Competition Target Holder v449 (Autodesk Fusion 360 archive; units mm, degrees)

design "Rifle Target Holder"
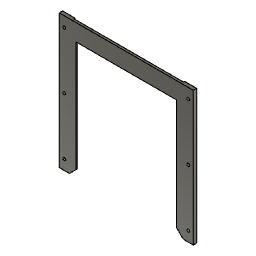
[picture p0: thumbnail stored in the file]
sketch "Sketch1" plane through (0, 0, 0) normal (0, 1, 0) x axis (1, 0, 0)
  line L1 (-174.5899, -63.5422) -> (-54.5899, -63.5422)
  line L2 (-174.5899, -183.5422) -> (-174.5899, -63.5422)
  line L3 (-54.5899, -183.5422) -> (-174.5899, -183.5422)
  line L4 (-54.5899, -63.5422) -> (-54.5899, -183.5422)
  line L5 (-69.5899, -168.5422) -> (-159.5899, -168.5422)
  line L6 (-69.5899, -78.5422) -> (-69.5899, -168.5422)
  line L7 (-159.5899, -78.5422) -> (-69.5899, -78.5422)
  line L8 (-159.5899, -168.5422) -> (-159.5899, -78.5422)
  line L9 (-159.5899, -183.5422) -> (-174.5899, -183.5422)
  line L10 (-174.5899, -183.5422) -> (-174.5899, -168.5422)
  point P2 (-54.5899, -63.5422)
  point P3 (-174.5899, -63.5422)
  point P5 (-54.5899, -183.5422)
  point P6 (-159.5899, -168.5422)
  point P7 (-69.5899, -168.5422)
  point P9 (-159.5899, -78.5422)
  point P4 (-174.5899, -183.5422)
  point P10 (-159.5899, -183.5422)
  point P11 (-174.5899, -168.5422)
  horizontal L1
  vertical L2
  horizontal L3
  vertical L4
  horizontal L5
  vertical L6
  horizontal L7
  vertical L8
  horizontal L9
  vertical L10
  dimension "d1" distance P2 P3 = 120
  dimension "d2" distance P2 P5 = 120
  dimension "d3" distance P6 P7 = 90
  dimension "d4" distance P6 P9 = 90
  dimension "d5" distance P4 P10 = 15
  dimension "d6" distance P4 P11 = 15
extrude "Extrude1" new body sketch "Sketch1" along normal blind 5
sketch "Sketch2" plane through (0, 0, 183.5422) normal (0, 0, 1) x axis (-1, 0, 0)
sketch "Sketch3" plane through (0, 0, 183.5422) normal (0, 0, 1) x axis (-1, 0, 0)
sketch "Sketch4" plane through (0, 0, 0) normal (0, 0, 1) x axis (1, 0, 0)
sketch "Sketch5" plane through (0, 0, 0) normal (0, 0, 1) x axis (1, 0, 0)
  line L1 (-63.5899, 5) -> (-165.5899, 5)
  line L2 (-63.5899, 3) -> (-63.5899, 5)
  line L3 (-165.5899, 3) -> (-63.5899, 3)
  line L4 (-165.5899, 5) -> (-165.5899, 3)
  line L5 (-174.5899, 5) -> (-54.5899, 5)
  point P2 (-165.5899, 5)
  point P3 (-63.5899, 5)
  point P5 (-165.5899, 3)
  horizontal L1
  vertical L2
  horizontal L3
  vertical L4
  midpoint L1 L5
  dimension "d14" distance P2 P3 = 102
  dimension "d15" distance P2 P5 = 2
extrude "Extrude2" cut sketch "Sketch5" to an object
sketch "Sketch6" plane through (0, 0, 183.5422) normal (0, 0, 1) x axis (-1, 0, 0)
  line L1 (63.5899, -3) -> (165.5899, -3)
  line L2 (63.5899, -4) -> (63.5899, -3)
  line L3 (165.5899, -4) -> (63.5899, -4)
  line L4 (165.5899, -3) -> (165.5899, -4)
  line L5 (63.5899, -3) -> (165.5899, -3)
  point P2 (165.5899, -3)
  point P3 (63.5899, -3)
  point P5 (165.5899, -4)
  horizontal L1
  vertical L2
  horizontal L3
  vertical L4
  midpoint L1 L5
  dimension "d18" distance P2 P3 = 102
  dimension "d19" distance P2 P5 = 1
extrude "Extrude3" add sketch "Sketch6" against normal blind 9
sketch "Sketch7" plane through (0, 5, 0) normal (0, 1, 0) x axis (-1, 0, 0)
  line L1 (63.5899, 183.5422) -> (63.5899, 63.5422)
  line L2 (54.5899, 183.5422) -> (63.5899, 183.5422)
  line L3 (54.5899, 63.5422) -> (54.5899, 183.5422)
  line L4 (63.5899, 63.5422) -> (54.5899, 63.5422)
  line L5 (69.5899, 168.5422) -> (159.5899, 168.5422)
  line L6 (159.5899, 78.5422) -> (69.5899, 78.5422)
  circle C1 centre (170.0899, 123.4348) radius 1.5
  circle C2 centre (170.0899, 174.4348) radius 1.5
  circle C3 centre (59.0899, 174.4348) radius 1.5
  circle C4 centre (170.0899, 72.4348) radius 1.5
  circle C5 centre (59.0899, 72.4348) radius 1.5
  circle C6 centre (59.0899, 123.4348) radius 1.5
  dimension "d34" diameter C1 = 3
  dimension "d35" diameter C2 = 3
  dimension "d36" diameter C3 = 3
  dimension "d37" diameter C4 = 3
  dimension "d38" diameter C5 = 3
  dimension "d39" diameter C6 = 3
extrude "Extrude4" cut sketch "Sketch7" profile of C1 C2 C3 C4 C5 C6 against normal blind 5
sketch "Sketch8" plane through (0, 0, 0) normal (0, 1, 0) x axis (1, 0, 0)
sketch "Sketch9" plane through (0, 4, 0) normal (0, 1, 0) x axis (-1, 0, 0)
sketch "Sketch10" plane through (0, 5, 0) normal (0, 1, 0) x axis (-1, 0, 0)
  line L1 (165.5899, 63.5422) -> (165.5899, 183.5422)
  line L2 (174.5899, 63.5422) -> (165.5899, 63.5422)
  line L3 (174.5899, 183.5422) -> (174.5899, 63.5422)
  line L4 (165.5899, 183.5422) -> (174.5899, 183.5422)
  line L5 (170.0899, 168.9348) -> (165.5899, 168.9348)
  line L6 (170.0899, 128.9348) -> (170.0899, 168.9348)
  line L7 (165.5899, 128.9348) -> (170.0899, 128.9348)
  line L8 (165.5899, 168.9348) -> (165.5899, 128.9348)
  line L9 (165.5899, 117.9348) -> (170.0899, 117.9348)
  line L10 (165.5899, 77.9348) -> (165.5899, 117.9348)
  line L11 (170.0899, 77.9348) -> (165.5899, 77.9348)
  line L12 (170.0899, 117.9348) -> (170.0899, 77.9348)
  circle C1 centre (170.0899, 72.4348) radius 1.5
  circle C2 centre (170.0899, 123.4348) radius 1.5
  circle C3 centre (170.0899, 174.4348) radius 1.5
  point P9 (165.5899, 168.9348)
  point P10 (170.0899, 168.9348)
  point P12 (165.5899, 128.9348)
  point P13 (170.0899, 117.9348)
  point P14 (165.5899, 117.9348)
  point P16 (170.0899, 77.9348)
  horizontal L5
  vertical L6
  horizontal L7
  vertical L8
  coincident L1 P9
  horizontal L9
  vertical L10
  horizontal L11
  vertical L12
  dimension "d44" distance P9 P10 = 4.5
  dimension "d45" distance P9 P12 = 40
  dimension "d46" distance P13 P14 = 4.5
  dimension "d47" distance P13 P16 = 40
extrude "Extrude5" cut sketch "Sketch10" profile of L1 L5 L6 L7 L8 L9 L10 L11 L12 against normal blind 2
sketch "Sketch11" plane through (0, 5, 0) normal (0, 1, 0) x axis (-1, 0, 0)
  line L1 (165.5899, 128.9348) -> (170.0899, 128.9348)
  line L2 (165.5899, 117.9348) -> (165.5899, 128.9348)
  line L3 (170.0899, 117.9348) -> (165.5899, 117.9348)
  line L4 (170.0899, 77.9348) -> (170.0899, 117.9348)
  line L5 (165.5899, 77.9348) -> (170.0899, 77.9348)
  line L6 (165.5899, 63.5422) -> (165.5899, 77.9348)
  line L7 (174.5899, 63.5422) -> (165.5899, 63.5422)
  line L8 (174.5899, 183.5422) -> (174.5899, 63.5422)
  line L9 (165.5899, 183.5422) -> (174.5899, 183.5422)
  line L10 (165.5899, 168.9348) -> (165.5899, 183.5422)
  line L11 (170.0899, 168.9348) -> (165.5899, 168.9348)
  line L12 (170.0899, 128.9348) -> (170.0899, 168.9348)
  line L13 (164.0899, 168.9348) -> (170.0899, 168.9348)
  line L14 (164.0899, 128.9348) -> (164.0899, 168.9348)
  line L15 (170.0899, 128.9348) -> (164.0899, 128.9348)
  line L16 (170.0899, 168.9348) -> (170.0899, 128.9348)
  line L17 (164.0899, 117.9348) -> (170.0899, 117.9348)
  line L18 (164.0899, 77.9348) -> (164.0899, 117.9348)
  line L19 (170.0899, 77.9348) -> (164.0899, 77.9348)
  line L20 (170.0899, 117.9348) -> (170.0899, 77.9348)
  circle C1 centre (170.0899, 72.4348) radius 1.5
  circle C2 centre (170.0899, 123.4348) radius 1.5
  circle C3 centre (170.0899, 174.4348) radius 1.5
  point P13 (170.0899, 168.9348)
  point P17 (170.0899, 168.9348)
  point P5 (170.0899, 117.9348)
  point P21 (170.0899, 117.9348)
  point P18 (164.0899, 168.9348)
  point P20 (170.0899, 128.9348)
  point P22 (164.0899, 117.9348)
  point P24 (170.0899, 77.9348)
  horizontal L13
  vertical L14
  horizontal L15
  vertical L16
  coincident P13 P17
  horizontal L17
  vertical L18
  horizontal L19
  vertical L20
  coincident P5 P21
  dimension "d50" distance P17 P18 = 6
  dimension "d51" distance P17 P20 = 40
  dimension "d52" distance P21 P22 = 6
  dimension "d53" distance P21 P24 = 40
extrude "Extrude6" cut sketch "Sketch11" profile of L1 L3 L4 L5 L11 L12 L13 L14 L15 L16 L17 L18 L19 L20 against normal blind 3
sketch "Sketch27" plane through (0, 0, 183.5422) normal (0, 0, 1) x axis (-1, 0, 0)
  line L1 (51.2268, 0) -> (175, 0)
  line L2 (51.2268, -2) -> (51.2268, 0)
  line L3 (175, -2) -> (51.2268, -2)
  line L4 (175, 0) -> (175, -2)
  point P2 (175, 0)
  point P5 (175, -2)
  horizontal L1
  vertical L2
  horizontal L3
  vertical L4
  dimension "d99" distance P2 P5 = 2
extrude "Extrude11" cut sketch "Sketch27" against normal blind 200
sketch "Sketch28" plane through (0, 2, 0) normal (0, -1, 0) x axis (1, 0, 0)
  line L1 (-174.5899, 63.5422) -> (-174.5899, 183.5422)
  line L2 (-54.5899, 63.5422) -> (-174.5899, 63.5422)
  line L3 (-54.5899, 183.5422) -> (-54.5899, 63.5422)
  line L4 (-174.5899, 183.5422) -> (-54.5899, 183.5422)
  line L5 (-164.0899, 77.9348) -> (-164.0899, 117.9348)
  line L6 (-170.0899, 77.9348) -> (-164.0899, 77.9348)
  line L7 (-170.0899, 117.9348) -> (-170.0899, 77.9348)
  line L8 (-164.0899, 117.9348) -> (-170.0899, 117.9348)
  line L9 (-170.0899, 168.9348) -> (-170.0899, 128.9348)
  line L10 (-164.0899, 168.9348) -> (-170.0899, 168.9348)
  line L11 (-164.0899, 128.9348) -> (-164.0899, 168.9348)
  line L12 (-170.0899, 128.9348) -> (-164.0899, 128.9348)
  line L13 (-159.5899, 78.5422) -> (-69.5899, 78.5422)
  line L14 (-159.5899, 168.5422) -> (-159.5899, 78.5422)
  line L15 (-69.5899, 168.5422) -> (-159.5899, 168.5422)
  line L16 (-69.5899, 78.5422) -> (-69.5899, 168.5422)
  line L17 (-164.0899, 168.9348) -> (-170.0899, 168.9348)
  line L18 (-164.0899, 128.9348) -> (-164.0899, 168.9348)
  line L19 (-170.0899, 128.9348) -> (-164.0899, 128.9348)
  line L20 (-170.0899, 168.9348) -> (-170.0899, 128.9348)
  line L21 (-164.0899, 117.9348) -> (-170.0899, 117.9348)
  line L22 (-164.0899, 77.9348) -> (-164.0899, 117.9348)
  line L23 (-170.0899, 77.9348) -> (-164.0899, 77.9348)
  line L24 (-170.0899, 117.9348) -> (-170.0899, 77.9348)
  circle C1 centre (-170.0899, 72.4348) radius 1.5
  circle C2 centre (-59.0899, 174.4348) radius 1.5
  circle C3 centre (-170.0899, 123.4348) radius 1.5
  circle C4 centre (-59.0899, 72.4348) radius 1.5
  circle C5 centre (-59.0899, 123.4348) radius 1.5
  circle C6 centre (-170.0899, 174.4348) radius 1.5
  point P13 (-164.0899, 128.9348)
  point P26 (-164.0899, 128.9348)
  point P11 (-170.0899, 168.9348)
  point P24 (-170.0899, 168.9348)
  point P7 (-164.0899, 77.9348)
  point P30 (-164.0899, 77.9348)
  point P9 (-170.0899, 117.9348)
  point P28 (-170.0899, 117.9348)
  horizontal L17
  vertical L18
  horizontal L19
  vertical L20
  coincident P13 P26
  coincident P11 P24
  horizontal L21
  vertical L22
  horizontal L23
  vertical L24
  coincident P7 P30
  coincident P9 P28
extrude "Extrude12" add sketch "Sketch28" profile of L5 L6 L7 L8 L9 L10 L11 L12 L17 L18 L19 L20 L21 L22 L23 L24 to an object
sketch "Sketch29" plane through (0, 5, 0) normal (0, 1, 0) x axis (-1, 0, 0)
sketch "Sketch30" plane through (0, 5, 0) normal (0, 1, 0) x axis (-1, 0, 0)
  line L1 (165.5899, 168.9348) -> (158.5899, 168.9348)
  line L2 (165.5899, 128.9348) -> (165.5899, 168.9348)
  line L3 (158.5899, 128.9348) -> (165.5899, 128.9348)
  line L4 (158.5899, 168.9348) -> (158.5899, 128.9348)
  line L5 (165.5899, 117.9348) -> (158.5899, 117.9348)
  line L6 (165.5899, 77.9348) -> (165.5899, 117.9348)
  line L7 (158.5899, 77.9348) -> (165.5899, 77.9348)
  line L8 (158.5899, 117.9348) -> (158.5899, 77.9348)
  point P3 (165.5899, 168.9348)
  point P6 (165.5899, 168.9348)
  point P8 (165.5899, 117.9348)
  point P11 (165.5899, 117.9348)
  point P2 (158.5899, 168.9348)
  point P5 (158.5899, 128.9348)
  point P7 (158.5899, 117.9348)
  point P10 (158.5899, 77.9348)
  horizontal L1
  vertical L2
  horizontal L3
  vertical L4
  coincident P3 P6
  horizontal L5
  vertical L6
  horizontal L7
  vertical L8
  coincident P8 P11
  dimension "d104" distance P2 P5 = 40
  dimension "d105" distance P7 P10 = 40
extrude "Extrude13" cut sketch "Sketch30" to an object
sketch "Sketch31" plane through (0, 3, 0) normal (0, 1, 0) x axis (-1, 0, 0)
  line L1 (159.5899, 78.5422) -> (159.5899, 168.5422)
  line L2 (69.5899, 78.5422) -> (159.5899, 78.5422)
  line L3 (69.5899, 168.5422) -> (69.5899, 78.5422)
  line L4 (159.5899, 168.5422) -> (69.5899, 168.5422)
  line L5 (165.5899, 174.5422) -> (165.5899, 63.5422)
  line L6 (63.5899, 174.5422) -> (165.5899, 174.5422)
  line L7 (63.5899, 63.5422) -> (63.5899, 174.5422)
  line L8 (165.5899, 63.5422) -> (63.5899, 63.5422)
  line L9 (159.5899, 78.5422) -> (69.5899, 78.5422)
  line L10 (159.5899, 55) -> (159.5899, 78.5422)
  line L11 (69.5899, 55) -> (159.5899, 55)
  line L12 (69.5899, 78.5422) -> (69.5899, 55)
  point P4 (69.5899, 78.5422)
  point P10 (69.5899, 78.5422)
  point P11 (159.5899, 78.5422)
  horizontal L9
  vertical L10
  horizontal L11
  vertical L12
  coincident P4 P10
  dimension "d108" distance P10 P11 = 90
extrude "Extrude14" cut sketch "Sketch31" profile of L2 L8 L9 L10 L12 to an object
sketch "Sketch32" plane through (0, 2, 0) normal (0, -1, 0) x axis (1, 0, 0)
  line L1 (-159.5899, 168.5422) -> (-159.5899, 63.5422)
  line L2 (-69.5899, 168.5422) -> (-159.5899, 168.5422)
  line L3 (-69.5899, 63.5422) -> (-69.5899, 168.5422)
  line L4 (-54.5899, 63.5422) -> (-69.5899, 63.5422)
  line L5 (-54.5899, 183.5422) -> (-54.5899, 63.5422)
  line L6 (-174.5899, 183.5422) -> (-54.5899, 183.5422)
  line L7 (-174.5899, 63.5422) -> (-174.5899, 183.5422)
  line L8 (-159.5899, 63.5422) -> (-174.5899, 63.5422)
  line L9 (-82.2581, 82.2104) -> (-63.5899, 63.5422)
  line L10 (-37.1892, 63.5422) -> (-63.5899, 63.5422)
  line L11 (-163.7719, 64.5857) -> (-163.7719, 63.5422)
  line L12 (-151.5827, 77.5225) -> (-165.563, 63.5422)
  line L13 (-185.334, 63.5422) -> (-165.563, 63.5422)
  line L14 (-151.5827, 77.5225) -> (-82.2581, 82.2104)
  line L15 (-165.563, 63.5422) -> (-63.5899, 63.5422)
  circle C1 centre (-170.0899, 174.4348) radius 1.5
  circle C2 centre (-59.0899, 123.4348) radius 1.5
  circle C3 centre (-59.0899, 72.4348) radius 1.5
  circle C4 centre (-170.0899, 123.4348) radius 1.5
  circle C5 centre (-59.0899, 174.4348) radius 1.5
  circle C6 centre (-170.0899, 72.4348) radius 1.5
  point P16 (-63.5899, 63.5422)
  point P19 (-63.5899, 63.5422)
  point P20 (-163.7719, 63.5422)
  point P22 (-165.563, 63.5422)
  horizontal L10
  coincident L4 P16
  coincident P16 P19
  coincident L8 P20
  perpendicular L8 L11
  horizontal L13
  coincident L8 P22
  dimension "d111" angle L9 L10 = 135
  dimension "d113" angle L12 L13 = 135
extrude "Extrude15" cut sketch "Sketch32" profile of L1 L3 L4 L8 L9 L12 L15 to an object
sketch "Sketch33" plane through (0, 4, 0) normal (0, 1, 0) x axis (-1, 0, 0)
  line L1 (63.5899, 183.5422) -> (165.5899, 183.5422)
  line L2 (63.5899, 174.5422) -> (63.5899, 183.5422)
  line L3 (165.5899, 174.5422) -> (63.5899, 174.5422)
  line L4 (165.5899, 183.5422) -> (165.5899, 174.5422)
  line L5 (160.5899, 183.5422) -> (68.5899, 183.5422)
  line L6 (160.5899, 168.5422) -> (160.5899, 183.5422)
  line L7 (68.5899, 168.5422) -> (160.5899, 168.5422)
  line L8 (68.5899, 183.5422) -> (68.5899, 168.5422)
  line L9 (68.5899, 183.5422) -> (63.5899, 183.5422)
  line L10 (68.5899, 174.5422) -> (68.5899, 183.5422)
  line L11 (63.5899, 174.5422) -> (68.5899, 174.5422)
  line L12 (63.5899, 183.5422) -> (63.5899, 174.5422)
  line L13 (160.5899, 183.5422) -> (165.5899, 183.5422)
  line L14 (160.5899, 174.5422) -> (160.5899, 183.5422)
  line L15 (165.5899, 174.5422) -> (160.5899, 174.5422)
  line L16 (165.5899, 183.5422) -> (165.5899, 174.5422)
  point P12 (68.5899, 174.5422)
  point P3 (63.5899, 183.5422)
  point P10 (63.5899, 183.5422)
  point P16 (160.5899, 174.5422)
  point P2 (165.5899, 183.5422)
  point P14 (165.5899, 183.5422)
  point P6 (68.5899, 183.5422)
  point P7 (160.5899, 183.5422)
  horizontal L5
  vertical L6
  horizontal L7
  vertical L8
  midpoint L1 L5
  horizontal L9
  vertical L10
  horizontal L11
  vertical L12
  coincident L3 P12
  coincident L8 P12
  coincident P3 P10
  horizontal L13
  vertical L14
  horizontal L15
  vertical L16
  coincident L3 P16
  coincident L6 P16
  coincident P2 P14
  dimension "d116" distance P6 P7 = 92
extrude "Extrude16" add sketch "Sketch33" profile of L1 L2 L3 L4 L6 L8 L9 L10 L11 L12 L13 L14 L15 L16 along normal blind 1
sketch "Sketch34" plane through (0, 4, 0) normal (0, 1, 0) x axis (-1, 0, 0)
  line L1 (160.5899, 183.5422) -> (160.5899, 174.5422)
  line L2 (68.5899, 183.5422) -> (160.5899, 183.5422)
  line L3 (68.5899, 174.5422) -> (68.5899, 183.5422)
  line L4 (160.5899, 174.5422) -> (68.5899, 174.5422)
  line L5 (163.5899, 168.5422) -> (65.5899, 168.5422)
  line L6 (163.5899, 183.5422) -> (163.5899, 168.5422)
  line L7 (65.5899, 183.5422) -> (163.5899, 183.5422)
  line L8 (65.5899, 168.5422) -> (65.5899, 183.5422)
  point P6 (65.5899, 168.5422)
  point P7 (163.5899, 168.5422)
  horizontal L5
  vertical L6
  horizontal L7
  vertical L8
  midpoint L2 L7
  dimension "d119" distance P6 P7 = 98
extrude "Extrude17" cut sketch "Sketch34" profile of L1 L3 L4 L5 L6 L7 L8 along normal blind 1
sketch "Sketch35" plane through (0, 5, 0) normal (0, 1, 0) x axis (-1, 0, 0)
  line L1 (163.5899, 174.5422) -> (163.5899, 183.5422)
  line L2 (165.5899, 174.5422) -> (163.5899, 174.5422)
  line L3 (165.5899, 63.5422) -> (165.5899, 174.5422)
  line L4 (174.5899, 63.5422) -> (165.5899, 63.5422)
  line L5 (174.5899, 183.5422) -> (174.5899, 63.5422)
  line L6 (163.5899, 183.5422) -> (174.5899, 183.5422)
  line L7 (170.0899, 123.4348) -> (170.0899, 174.4348)
  line L8 (170.0899, 72.4348) -> (170.0899, 123.4348)
  line L9 (144.5169, 151.2369) -> (170.0899, 151.2369)
  line L10 (144.5169, 97.9348) -> (170.0899, 97.9348)
  circle C1 centre (170.0899, 174.4348) radius 1.5
  circle C2 centre (170.0899, 123.4348) radius 1.5
  circle C3 centre (170.0899, 72.4348) radius 1.5
  circle C4 centre (165.5899, 151.2369) radius 1
  circle C5 centre (165.5899, 97.9348) radius 1
  point P2 (170.0899, 174.4348)
  point P11 (170.0899, 174.4348)
  point P3 (170.0899, 123.4348)
  point P12 (170.0899, 123.4348)
  point P4 (170.0899, 72.4348)
  point P13 (170.0899, 72.4348)
  point P14 (170.0899, 151.2369)
  point P16 (170.0899, 97.9348)
  point P18 (165.5899, 151.2369)
  point P19 (165.5899, 97.9348)
  coincident P2 P11
  coincident P3 P12
  coincident P4 P13
  coincident L7 P14
  perpendicular L7 L9
  midpoint L8 P16
  perpendicular L8 L10
  coincident L3 P18
  coincident L9 P18
  coincident L3 P19
  coincident L10 P19
  dimension "d122" diameter C4 = 2
  dimension "d123" diameter C5 = 2
sketch "Sketch36" plane through (0, 5, 0) normal (0, 1, 0) x axis (-1, 0, 0)
extrude "Extrude18" add sketch "Sketch35" profile of L3 L9 L10 C4 C5 against normal blind 2
component_from_bodies "Body->Comp"
sketch "Sketch37" plane through (-0.905, 2, 7.1802) normal (0, -1, 0) x axis (1, 0, 0)
  line L1 (-62.685, 56.362) -> (-68.685, 62.362)
  line L2 (-53.685, 56.362) -> (-62.685, 56.362)
  line L3 (-53.685, 176.362) -> (-53.685, 56.362)
  line L4 (-173.685, 176.362) -> (-53.685, 176.362)
  line L5 (-173.685, 56.362) -> (-173.685, 176.362)
  line L6 (-164.658, 56.362) -> (-173.685, 56.362)
  line L7 (-158.685, 62.3351) -> (-164.658, 56.362)
  line L8 (-158.685, 161.362) -> (-158.685, 62.3351)
  line L9 (-68.685, 161.362) -> (-158.685, 161.362)
  line L10 (-68.685, 62.362) -> (-68.685, 161.362)
  circle C1 centre (-169.185, 167.2546) radius 1.5
  circle C2 centre (-58.185, 116.2546) radius 1.5
  circle C3 centre (-58.185, 65.2546) radius 1.5
  circle C4 centre (-169.185, 116.2546) radius 1.5
  circle C5 centre (-58.185, 167.2546) radius 1.5
  circle C6 centre (-169.185, 65.2546) radius 1.5
  circle C7 centre (-169.185, 167.2546) radius 1.25
  circle C8 centre (-169.185, 116.2546) radius 1.25
  circle C9 centre (-169.185, 65.2546) radius 1.25
  circle C10 centre (-58.185, 167.2546) radius 1.25
  circle C11 centre (-58.185, 116.2546) radius 1.25
  circle C12 centre (-58.185, 65.2546) radius 1.25
  concentric C1 C7
  concentric C4 C8
  concentric C6 C9
  concentric C5 C10
  concentric C2 C11
  concentric C3 C12
  dimension "d126" diameter C7 = 2.5
  dimension "d127" diameter C8 = 2.5
  dimension "d128" diameter C9 = 2.5
  dimension "d129" diameter C10 = 2.5
  dimension "d130" diameter C11 = 2.5
  dimension "d131" diameter C12 = 2.5
extrude "Extrude1" add sketch "Sketch37" profile of C1 C2 C3 C4 C5 C6 C7 C8 C9 C10 C11 C12 to an object
sketch "Sketch38" plane through (0, 5, 0) normal (0, 1, 0) x axis (-1, 0, 0)
  line L1 (163.5899, 174.5422) -> (163.5899, 183.5422)
  line L2 (165.5899, 174.5422) -> (163.5899, 174.5422)
  line L3 (165.5899, 152.2369) -> (165.5899, 174.5422)
  line L4 (165.5899, 98.9348) -> (165.5899, 150.2369)
  line L5 (165.5899, 63.5422) -> (165.5899, 96.9348)
  line L6 (174.5899, 63.5422) -> (165.5899, 63.5422)
  line L7 (174.5899, 183.5422) -> (174.5899, 63.5422)
  line L8 (163.5899, 183.5422) -> (174.5899, 183.5422)
  line L9 (163.0339, 152.2369) -> (165.5899, 152.2369)
  line L10 (163.0339, 150.2369) -> (163.0339, 152.2369)
  line L11 (165.5899, 150.2369) -> (163.0339, 150.2369)
  line L12 (165.5899, 152.2369) -> (165.5899, 150.2369)
  line L13 (163.3156, 98.9348) -> (165.5899, 98.9348)
  line L14 (163.3156, 96.9348) -> (163.3156, 98.9348)
  line L15 (165.5899, 96.9348) -> (163.3156, 96.9348)
  line L16 (165.5899, 98.9348) -> (165.5899, 96.9348)
  circle C1 centre (170.0899, 123.4348) radius 1.25
  circle C2 centre (170.0899, 72.4348) radius 1.25
  circle C3 centre (170.0899, 174.4348) radius 1.25
  arc A1 centre (165.5899, 151.2369) radius 1 clockwise from (165.5899, 150.2369) to (165.5899, 152.2369)
  arc A2 centre (165.5899, 97.9348) radius 1 clockwise from (165.5899, 96.9348) to (165.5899, 98.9348)
  point P8 (165.5899, 152.2369)
  point P17 (165.5899, 152.2369)
  point P11 (165.5899, 98.9348)
  point P21 (165.5899, 98.9348)
  horizontal L9
  vertical L10
  horizontal L11
  vertical L12
  coincident P8 P17
  horizontal L13
  vertical L14
  horizontal L15
  vertical L16
  coincident P11 P21
extrude "Extrude2" cut sketch "Sketch38" profile of A1 A2 L12 L16 to an object
sketch "Sketch39" plane through (0, 5, 0) normal (0, 1, 0) x axis (-1, 0, 0)
  line L1 (165.5899, 63.5422) -> (165.5899, 174.5422)
  line L2 (174.5899, 63.5422) -> (165.5899, 63.5422)
  line L3 (174.5899, 183.5422) -> (174.5899, 63.5422)
  line L4 (163.5899, 183.5422) -> (174.5899, 183.5422)
  line L5 (163.5899, 174.5422) -> (163.5899, 183.5422)
  line L6 (165.5899, 174.5422) -> (163.5899, 174.5422)
  line L7 (170.0899, 123.4348) -> (170.0899, 174.4348)
  line L8 (170.0899, 72.4348) -> (170.0899, 123.4348)
  circle C1 centre (170.0899, 174.4348) radius 1.25
  circle C2 centre (170.0899, 72.4348) radius 1.25
  circle C3 centre (170.0899, 123.4348) radius 1.25
  circle C4 centre (170.0899, 148.9348) radius 5
  circle C5 centre (170.0899, 97.9348) radius 5
  point P8 (170.0899, 174.4348)
  point P11 (170.0899, 174.4348)
  point P10 (170.0899, 123.4348)
  point P12 (170.0899, 123.4348)
  point P9 (170.0899, 72.4348)
  point P13 (170.0899, 72.4348)
  point P14 (170.0899, 148.9348)
  point P15 (170.0899, 97.9348)
  coincident P8 P11
  coincident P10 P12
  coincident P9 P13
  midpoint L7 P14
  midpoint L8 P15
  dimension "d136" diameter C4 = 10
  dimension "d137" diameter C5 = 10
extrude "Extrude3" add sketch "Sketch39" profile of L1 C4 C5 to an object
sketch "Sketch12" plane through (0, 2, 0) normal (0, 1, 0) x axis (-1, 0, 0)
  line L1 (170.0899, 168.9348) -> (170.0899, 128.9348)
  line L2 (164.0899, 168.9348) -> (170.0899, 168.9348)
  line L3 (164.0899, 128.9348) -> (164.0899, 168.9348)
  line L4 (170.0899, 128.9348) -> (164.0899, 128.9348)
sketch "Sketch13" plane through (0, 2, 0) normal (0, 1, 0) x axis (-1, 0, 0)
sketch "Sketch14" plane through (0, 2, 0) normal (0, 1, 0) x axis (-1, 0, 0)
  curve K1 (145.3051, 123.914) -> (145.3051, 159.914)
  curve K2 (148.3051, 141.914) -> (142.3051, 141.914)
  line L1 (155.7161, 141.914) -> (145.3051, 141.914)
  curve K3 (145.3051, 124.914) -> (145.3051, 158.914)
  curve K4 (147.3051, 141.914) -> (143.3051, 141.914)
  line L2 (162.3051, 141.914) -> (145.3051, 141.914)
  curve K5 (101.5476, 123.3804) -> (101.5476, 159.3804)
  curve K6 (104.5476, 141.3804) -> (98.5476, 141.3804)
  curve K7 (101.5476, 124.3804) -> (101.5476, 158.3804)
  curve K8 (103.5476, 141.3804) -> (99.5476, 141.3804)
  closed curve K9 centre (145.3051, 141.914)
  closed curve K10 centre (145.3051, 141.914)
  closed curve K11 centre (101.5476, 141.3804)
  closed curve K12 centre (101.5476, 141.3804)
  point P3 (145.3051, 159.914)
  point P4 (145.3051, 123.914)
  point P5 (142.3051, 141.914)
  point P6 (148.3051, 141.914)
  point P9 (145.3051, 158.914)
  point P10 (145.3051, 124.914)
  point P11 (143.3051, 141.914)
  point P12 (147.3051, 141.914)
  point P16 (101.5476, 159.3804)
  point P17 (101.5476, 123.3804)
  point P18 (98.5476, 141.3804)
  point P19 (104.5476, 141.3804)
  point P20 (101.5476, 158.3804)
  point P21 (101.5476, 124.3804)
  point P22 (99.5476, 141.3804)
  point P23 (103.5476, 141.3804)
  coincident K9 P3
  coincident K9 P4
  coincident K9 P5
  coincident K9 P6
  horizontal L1
  coincident K10 P9
  coincident K10 P10
  coincident K10 P11
  coincident K10 P12
  horizontal L2
  concentric K9 K10
  coincident K11 P16
  coincident K11 P17
  coincident K11 P18
  coincident K11 P19
  coincident K12 P20
  coincident K12 P21
  coincident K12 P22
  coincident K12 P23
  concentric K11 K12
  dimension "d62" distance K9 = 36
  dimension "d63" angle K1 L1 = 90
  dimension "d64" = 6
  dimension "d65" distance K10 = 34
  dimension "d66" angle K3 L2 = 90
  dimension "d67" = 4
  dimension "d68" distance K11 = 36
  dimension "d69" = 6
  dimension "d70" distance K12 = 34
  dimension "d71" = 4
sketch "Sketch15" plane through (0, 0, 0) normal (0, -1, 0) x axis (1, 0, 0)
  line L1 (-159.5899, 168.5422) -> (-159.5899, 78.5422)
  line L2 (-69.5899, 168.5422) -> (-159.5899, 168.5422)
  line L3 (-69.5899, 78.5422) -> (-69.5899, 168.5422)
  line L4 (-159.5899, 78.5422) -> (-69.5899, 78.5422)
  line L5 (-174.5899, 63.5422) -> (-174.5899, 183.5422)
  line L6 (-54.5899, 63.5422) -> (-174.5899, 63.5422)
  line L7 (-54.5899, 183.5422) -> (-54.5899, 63.5422)
  line L8 (-174.5899, 183.5422) -> (-54.5899, 183.5422)
  curve K1 (-124.7483, 114.0838) -> (-124.7483, 150.0838)
  curve K2 (-121.7483, 132.0838) -> (-127.7483, 132.0838)
  curve K3 (-124.7483, 115.0838) -> (-124.7483, 149.0838)
  curve K4 (-122.7483, 132.0838) -> (-126.7483, 132.0838)
  line L9 (-107.7483, 132.0838) -> (-124.7483, 132.0838)
  circle C1 centre (-170.0899, 72.4348) radius 1.5
  circle C2 centre (-59.0899, 174.4348) radius 1.5
  circle C3 centre (-170.0899, 123.4348) radius 1.5
  circle C4 centre (-59.0899, 72.4348) radius 1.5
  circle C5 centre (-59.0899, 123.4348) radius 1.5
  circle C6 centre (-170.0899, 174.4348) radius 1.5
  closed curve K5 centre (-124.7483, 132.0838)
  closed curve K6 centre (-124.7483, 132.0838)
  point P17 (-124.7483, 150.0838)
  point P18 (-124.7483, 114.0838)
  point P19 (-127.7483, 132.0838)
  point P20 (-121.7483, 132.0838)
  point P22 (-124.7483, 149.0838)
  point P23 (-124.7483, 115.0838)
  point P24 (-126.7483, 132.0838)
  point P25 (-122.7483, 132.0838)
  vertical K1
  coincident K5 P17
  coincident K5 P18
  coincident K5 P19
  coincident K5 P20
  coincident K6 P22
  coincident K6 P23
  coincident K6 P24
  coincident K6 P25
  horizontal L9
  concentric K5 K6
  dimension "d74" distance K5 = 36
  dimension "d75" = 6
  dimension "d76" distance K6 = 34
  dimension "d77" angle K3 L9 = 90
  dimension "d78" = 4
sketch "Sketch16" plane through (0, 0, 0) normal (0, -1, 0) x axis (1, 0, 0)
  line L1 (-159.5899, 168.5422) -> (-159.5899, 78.5422)
  line L2 (-69.5899, 168.5422) -> (-159.5899, 168.5422)
  line L3 (-69.5899, 78.5422) -> (-69.5899, 168.5422)
  line L4 (-159.5899, 78.5422) -> (-69.5899, 78.5422)
  line L5 (-174.5899, 63.5422) -> (-174.5899, 183.5422)
  line L6 (-54.5899, 63.5422) -> (-174.5899, 63.5422)
  line L7 (-54.5899, 183.5422) -> (-54.5899, 63.5422)
  line L8 (-174.5899, 183.5422) -> (-54.5899, 183.5422)
  curve K1 (-142.3117, 124.7525) -> (-142.3117, 160.7525)
  curve K2 (-139.3117, 142.7525) -> (-145.3117, 142.7525)
  line L9 (-122, 142.7525) -> (-142.3117, 142.7525)
  curve K3 (-142.3117, 125.7525) -> (-142.3117, 159.7525)
  curve K4 (-140.3117, 142.7525) -> (-144.3117, 142.7525)
  line L10 (-125.3117, 142.7525) -> (-142.3117, 142.7525)
  curve K5 (-105.259, 124.7525) -> (-105.259, 160.7525)
  curve K6 (-102.259, 142.7525) -> (-108.259, 142.7525)
  line L11 (-87.259, 142.7525) -> (-105.259, 142.7525)
  curve K7 (-105.259, 125.7525) -> (-105.259, 159.7525)
  curve K8 (-103.259, 142.7525) -> (-107.259, 142.7525)
  line L12 (-88.259, 142.7525) -> (-105.259, 142.7525)
  circle C1 centre (-170.0899, 72.4348) radius 1.5
  circle C2 centre (-59.0899, 174.4348) radius 1.5
  circle C3 centre (-170.0899, 123.4348) radius 1.5
  circle C4 centre (-59.0899, 72.4348) radius 1.5
  circle C5 centre (-59.0899, 123.4348) radius 1.5
  circle C6 centre (-170.0899, 174.4348) radius 1.5
  closed curve K9 centre (-142.3117, 142.7525)
  closed curve K10 centre (-142.3117, 142.7525)
  closed curve K11 centre (-105.259, 142.7525)
  closed curve K12 centre (-105.259, 142.7525)
  point P17 (-142.3117, 160.7525)
  point P18 (-142.3117, 124.7525)
  point P19 (-145.3117, 142.7525)
  point P20 (-139.3117, 142.7525)
  point P23 (-142.3117, 159.7525)
  point P24 (-142.3117, 125.7525)
  point P25 (-144.3117, 142.7525)
  point P26 (-140.3117, 142.7525)
  point P29 (-105.259, 160.7525)
  point P30 (-105.259, 124.7525)
  point P31 (-108.259, 142.7525)
  point P32 (-102.259, 142.7525)
  point P35 (-105.259, 159.7525)
  point P36 (-105.259, 125.7525)
  point P37 (-107.259, 142.7525)
  point P38 (-103.259, 142.7525)
  coincident K9 P17
  coincident K9 P18
  coincident K9 P19
  coincident K9 P20
  horizontal L9
  coincident K10 P23
  coincident K10 P24
  coincident K10 P25
  coincident K10 P26
  horizontal L10
  concentric K9 K10
  coincident K11 P29
  coincident K11 P30
  coincident K11 P31
  coincident K11 P32
  horizontal L11
  coincident K12 P35
  coincident K12 P36
  coincident K12 P37
  coincident K12 P38
  horizontal L12
  concentric K11 K12
  dimension "d81" distance K9 = 36
  dimension "d82" angle K1 L9 = 90
  dimension "d83" = 6
  dimension "d84" distance K10 = 34
  dimension "d85" angle K3 L10 = 90
  dimension "d86" = 4
  dimension "d87" distance K11 = 36
  dimension "d88" angle K5 L11 = 90
  dimension "d89" = 6
  dimension "d90" distance K12 = 34
  dimension "d91" angle K7 L12 = 90
  dimension "d92" = 4
extrude "Extrude9" new body sketch "Sketch16" profile of K9 K10 K11 K12 against normal blind 2.5
sketch "Sketch17" plane through (0, 0, 0) normal (0, -1, 0) x axis (1, 0, 0)
  line L1 (-159.5899, 168.5422) -> (-159.5899, 78.5422)
  line L2 (-69.5899, 168.5422) -> (-159.5899, 168.5422)
  line L3 (-69.5899, 78.5422) -> (-69.5899, 168.5422)
  line L4 (-159.5899, 78.5422) -> (-69.5899, 78.5422)
  line L5 (-174.5899, 63.5422) -> (-174.5899, 183.5422)
  line L6 (-54.5899, 63.5422) -> (-174.5899, 63.5422)
  line L7 (-54.5899, 183.5422) -> (-54.5899, 63.5422)
  line L8 (-174.5899, 183.5422) -> (-54.5899, 183.5422)
  curve K1
  curve K2
  curve K3
  curve K4
  circle C1 centre (-170.0899, 72.4348) radius 1.5
  circle C2 centre (-59.0899, 174.4348) radius 1.5
  circle C3 centre (-170.0899, 123.4348) radius 1.5
  circle C4 centre (-59.0899, 72.4348) radius 1.5
  circle C5 centre (-59.0899, 123.4348) radius 1.5
  circle C6 centre (-170.0899, 174.4348) radius 1.5
  coincident L8
  dimension "d96" Text1-Height = 5
sketch "Sketch18" plane through (0, 0, 0) normal (0, -1, 0) x axis (1, 0, 0)
extrude "Extrude10" cut sketch "Sketch17" against normal blind 1
sketch "Sketch19" plane through (0, 0, 0) normal (1, 0, 0) x axis (0, 1, 0)
sketch "Sketch20" plane through (0, 2.5, 0) normal (0, 1, 0) x axis (-1, 0, 0)
sketch "Sketch21" plane through (0, 2.5, 0) normal (0, 1, 0) x axis (-1, 0, 0)
sketch "Sketch22" plane through (0, 5, 0) normal (0, 1, 0) x axis (-1, 0, 0)
  line L1 (63.5899, 183.5422) -> (63.5899, 63.5422)
  line L2 (54.5899, 183.5422) -> (63.5899, 183.5422)
  line L3 (54.5899, 63.5422) -> (54.5899, 183.5422)
  line L4 (63.5899, 63.5422) -> (54.5899, 63.5422)
  circle C1 centre (59.0899, 174.4348) radius 1.5
  circle C2 centre (59.0899, 72.4348) radius 1.5
  circle C3 centre (59.0899, 123.4348) radius 1.5
sketch "Sketch23" plane through (0, 2.5, 0) normal (0, 1, 0) x axis (-1, 0, 0)
  closed curve K1 centre (142.3117, 142.7525)
sketch "Sketch24" plane through (0, 0, 0) normal (0, 1, 0) x axis (1, 0, 0)
sketch "Sketch25" plane through (0, 2.5, 0) normal (0, 1, 0) x axis (-1, 0, 0)
sketch "Sketch26" plane through (0, 2.5, 0) normal (0, 1, 0) x axis (-1, 0, 0)
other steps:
base_feature "Base Feature"
create_component "CreateComponent1"
remove_body "RemoveBody1"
